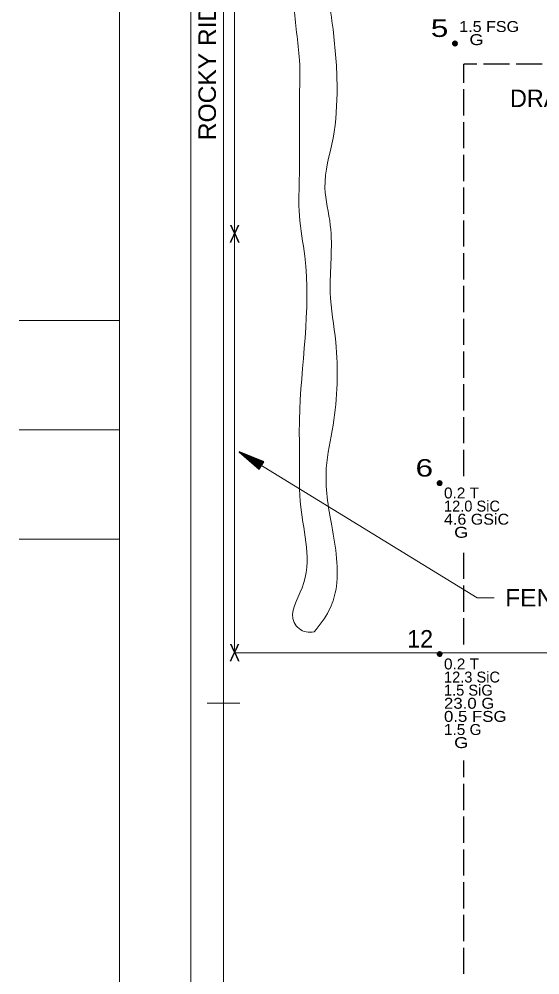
# Model space of a CAD drawing. Extents: x -496 to 480, y -450 to 700.
# Drawn here: x -496.1 to -257.6, y -124.4 to 312.9 of the extents above; entities that cross this region are included whole.
import ezdxf
from ezdxf.enums import TextEntityAlignment as Align

# ---------------------------------------------------------------- set-up
doc = ezdxf.new("R2010")
doc.units = 0
doc.header["$LTSCALE"] = 2
doc.linetypes.add('LONG_DASHED', pattern=[7.5, 6, -1.5])
for name, color, linetype, lineweight in [('1', 7, 'Continuous', 13), ('2', 7, 'Continuous', 35), ('3', 7, 'Continuous', 13), ('4', 7, 'Continuous', 25)]:
    doc.layers.add(name, color=color, linetype=linetype, lineweight=lineweight)

msp = doc.modelspace()

# ---------------------------------------------------------------- linework, layer by layer
at = {"layer": '1'}
for p, q in [((-402.391, 402.339), (-402.391, -402.333)), ((-450.017, 174.973), (-496.057, 174.973)), ((-450.017, 124.973), (-496.057, 124.973)), ((-450.017, 74.973), (-496.057, 74.973)), ((-395.017, -0.027), (-410.017, -0.027))]:
    msp.add_line(p, q, dxfattribs=at)
msp.add_lwpolyline([(449.983, -450.027), (449.983, 399.973), (449.983, 699.973), (-450.017, 699.973), (-450.017, 49.973), (-450.017, -450.027)], dxfattribs=at)
at = {"layer": '2', "linetype": 'LONG_DASHED', "lineweight": 25}
for p, q in [((-292.391, 103.827), (-292.391, 292.339)), ((-106.483, 292.339), (-292.391, 292.339)), ((-292.391, 26.78), (-292.391, 71.374)), ((-292.391, -123.968), (-292.391, -26.329))]:
    msp.add_line(p, q, dxfattribs=at)
at = {"layer": '2'}
for centre in [(-296.511, 301.781), (-303.504, 100.605), (-303.504, 22.37)]:
    msp.add_circle(centre, 1, dxfattribs=at)
for points in [[(-296.522, 302.668), (-295.791, 302.263), (-295.64, 301.415), (-296.325, 300.887), (-297.134, 301.117), (-297.42, 301.876), (-297.173, 302.437), (-296.6, 302.606), (-295.926, 302.112), (-295.943, 301.37), (-296.46, 301.112), (-296.982, 301.28), (-297.207, 301.926), (-296.623, 302.392), (-296.185, 301.859), (-296.224, 301.376), (-296.853, 301.511), (-296.707, 302.145), (-296.415, 301.595)], [(-303.515, 101.492), (-302.785, 101.088), (-302.633, 100.24), (-303.318, 99.712), (-304.127, 99.942), (-304.414, 100.7), (-304.167, 101.262), (-303.594, 101.43), (-302.92, 100.936), (-302.936, 100.195), (-303.453, 99.936), (-303.976, 100.105), (-304.2, 100.751), (-303.616, 101.217), (-303.178, 100.683), (-303.217, 100.2), (-303.846, 100.335), (-303.7, 100.97), (-303.408, 100.419)], [(-303.515, 23.257), (-302.785, 22.853), (-302.633, 22.005), (-303.318, 21.477), (-304.127, 21.707), (-304.414, 22.465), (-304.167, 23.027), (-303.594, 23.196), (-302.92, 22.701), (-302.936, 21.96), (-303.453, 21.702), (-303.976, 21.87), (-304.2, 22.516), (-303.616, 22.982), (-303.178, 22.449), (-303.217, 21.965), (-303.846, 22.1), (-303.7, 22.735), (-303.408, 22.185)]]:
    msp.add_spline(points, degree=3, dxfattribs=at)
at = {"layer": '3'}
for p, q in [((-417.391, 402.339), (-417.391, -402.333)), ((324.354, 23.005), (-397.391, 23.005))]:
    msp.add_line(p, q, dxfattribs=at)
msp.add_lwpolyline([(410.562, 397.339), (-397.391, 397.339), (-397.391, 23.005)], dxfattribs=at)
for points in [[(-360.928, 32.503), (-364.618, 32.503), (-370.152, 36.803), (-366.462, 52.771), (-367.077, 89.622), (-367.692, 111.733), (-367.692, 129.544), (-365.233, 204.474), (-367.692, 222.9), (-367.692, 241.939), (-367.692, 275.719), (-367.692, 294.145), (-370.152, 319.326), (-368.307, 346.964), (-367.077, 354.949), (-364.003, 361.705), (-358.469, 367.232), (-350.475, 372.146), (-328.339, 369.075), (-249.018, 367.232), (-212.739, 369.075), (-184.454, 370.303), (-156.784, 369.075), (-126.039, 369.689), (-110.052, 371.532), (-86.686, 369.689), (-25.196, 366.618), (-14.128, 369.075), (5.548, 370.303), (27.07, 370.918), (45.517, 368.461), (60.889, 369.075)], [(-360.928, 32.503), (-354.165, 42.33), (-351.09, 51.543), (-352.935, 81.024), (-355.394, 107.433), (-352.32, 127.087), (-351.09, 165.167), (-353.55, 187.891), (-353.55, 218.6), (-356.009, 235.798), (-352.32, 258.522), (-350.475, 281.861), (-352.32, 308.271), (-354.165, 323.011), (-355.394, 336.523), (-355.394, 346.964), (-351.705, 352.492), (-338.792, 357.406), (-308.048, 357.406), (-285.911, 359.862), (-274.228, 356.791), (-261.93, 352.492), (-249.018, 349.421), (-239.179, 350.65), (-224.422, 355.563), (-221.347, 356.177), (-209.664, 351.264), (-194.292, 346.964), (-171.541, 347.579), (-160.473, 350.65), (-154.939, 353.72), (-145.101, 357.406), (-140.796, 358.634), (-130.958, 358.634), (-102.673, 358.02), (-94.064, 356.791), (-86.686, 353.72), (-69.469, 350.035), (-56.556, 344.508), (-35.035, 344.508), (-21.507, 347.579), (-10.439, 346.964), (8.623, 345.736), (21.536, 349.421), (27.07, 352.492), (41.212, 356.177), (52.895, 357.406)], [(-128.313, 18.951), (-125.783, 0.424), (-109.764, -29.051), (-106.391, -45.052), (-103.019, -54.316), (-97.96, -66.106), (-91.215, -85.475), (-81.941, -105.686), (-81.941, -117.476), (-84.47, -135.161), (-90.372, -165.478), (-92.058, -189.058), (-98.803, -201.691), (-111.45, -230.324), (-133.371, -253.061), (-142.646, -263.167), (-157.822, -273.273), (-183.115, -284.221), (-215.154, -299.379), (-232.859, -301.064), (-256.467, -300.221), (-272.486, -305.274), (-287.662, -311.169), (-297.78, -312.854), (-318.014, -311.169), (-339.936, -301.906), (-352.582, -299.379), (-370.288, -290.958), (-384.621, -289.274), (-392.209, -288.431), (-393.895, -284.221)]]:
    msp.add_spline(points, degree=3, dxfattribs=at)
at = {"layer": '4', "lineweight": 13}
msp.add_lwpolyline([(-278.491, 48.154), (-286.244, 48.154), (-395.277, 114.951)], dxfattribs=at)
at = {"layer": '4'}
msp.add_lwpolyline([(-395.277, 114.951), (-386.089, 106.977), (-384, 110.387)], close=True, dxfattribs=at)
msp.add_lwpolyline([(-386.111, 107.129), (-394.788, 114.65), (-384.225, 110.332), (-386.058, 107.3), (-394.16, 114.265), (-384.48, 110.288), (-386.125, 107.518), (-393.497, 113.859), (-384.76, 110.204), (-386.124, 107.769), (-392.753, 113.379), (-385.065, 110.163), (-386.195, 108.069), (-391.861, 112.805), (-385.366, 110.043), (-386.244, 108.402), (-390.896, 112.189), (-385.774, 109.913), (-386.341, 108.739), (-389.859, 111.478), (-386.204, 109.872), (-386.482, 109.13), (-388.577, 110.717), (-386.727, 109.763)], dxfattribs=at)

# ---------------------------------------------------------------- texts
at = {"layer": '2', "width": 1.35}
for s, p in [('  5', (-299.511, 304.781)), ('  6', (-306.505, 103.605))]:
    msp.add_text(s, height=8, dxfattribs=at).set_placement(p, align=Align.RIGHT)
at = {"layer": '2'}
for s, width, p in [('1.5 FSG    ', 1.1, (-294.511, 307.044)), ('  G        ', 1.25, (-294.511, 301.044)), ('0.2 T      ', 1.05, (-301.504, 93.605)), ('4.6 GSiC   ', 1.1, (-301.504, 81.605)), ('  G        ', 1.25, (-301.504, 75.605)), ('0.2 T      ', 1.05, (-301.504, 15.37)), ('23.0 G     ', 1.15, (-301.504, -2.63)), ('0.5 FSG    ', 1.15, (-301.504, -8.63)), ('1.5 G      ', 1.05, (-301.504, -14.63)), ('  G        ', 1.25, (-301.504, -20.63))]:
    msp.add_text(s, height=5, dxfattribs=dict(at, width=width)).set_placement(p)
for s, p in [('12.0 SiC   ', (-301.504, 87.605)), ('12.3 SiC   ', (-301.504, 9.37)), ('1.5 SiG    ', (-301.504, 3.37))]:
    msp.add_text(s, height=5, dxfattribs=at).set_placement(p)
msp.add_text(' 12', height=8, dxfattribs=at).set_placement((-306.505, 25.37), align=Align.RIGHT)
at = {"layer": '3', "width": 0.7}
for p in [(-397.37, 210.716), (-397.396, 19.049)]:
    msp.add_text('X', height=8, dxfattribs=at).set_placement(p, align=Align.CENTER)
at = {"layer": '4', "width": 1.05}
msp.add_text('ROCKY RIDGE ROAD', height=8, rotation=90, dxfattribs=at).set_placement((-405.943, 314.64), align=Align.CENTER)
at = {"layer": '4'}
msp.add_text('DRAINAGE COURSE(E/W)', height=8, dxfattribs=at).set_placement((-205.301, 272.684), align=Align.CENTER)
at = {"layer": '4', "width": 1.05}
msp.add_text('FENCE LINE', height=8, dxfattribs=at).set_placement((-240.416, 44.159), align=Align.CENTER)

doc.saveas('drawing.dxf')
